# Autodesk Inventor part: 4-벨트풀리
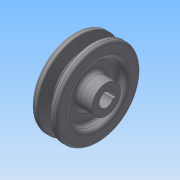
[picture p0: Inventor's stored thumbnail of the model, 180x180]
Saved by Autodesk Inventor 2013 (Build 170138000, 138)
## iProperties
Created: 2015-02
Part Number: 4-벨트풀리
Material: 일반
Document SubType Name: Modeling
Designer: Administrator
Density: 1 g/cm^3
Author: Administrator
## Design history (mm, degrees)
sketch "스케치1"
  geometry: L1 (0, 0)-(25, 0); L2 (0, 0)-(0, 11); L3 (0, 11)-(6, 11); L4 (6, 11)-(6, 21.5); L5 (6, 21.5)-(0, 21.5); L6 (0, 21.5)-(0, 32.5); L7 (0, 32.5)-(4.675, 32.5); L8 (4.675, 32.5)-(7.426, 23.5); L9 (7.426, 23.5)-(11.574, 23.5); L10 (11.574, 23.5)-(14.325, 32.5); L11 (14.325, 32.5)-(19, 32.5); L12 (19, 32.5)-(19, 21.5); L13 (19, 21.5)-(13, 21.5); L14 (13, 21.5)-(13, 11); L15 (13, 11)-(25, 11); L16 (25, 11)-(25, 0); 2 further points
  constraints: 32 end point, 6 parallel, 6 perpendicular, 5 collinear, 3 equal length, 2 point on line, 1 horizontal, 1 horizontal alignment
  dimensions: "d0" = 25 distance of L1.start L1.end; "d1" = 43 diameter of L5 L1; "d2" = 22 diameter of L3 L1; "d3" = 6 distance of L4.end L5.end; "d4" = 19 distance between parallel lines of L6 L12; "d5" = 65 diameter of L7 L1; "d6" = 8 distance of point (13.5, 29.8) point (5.5, 29.8); "d7" = 34 deg angle of L10 L8; "d8" = 2.7 distance from line of L11 point (13.5, 29.8); "d9" = 6.3 distance from line of point (13.5, 29.8) L9
revolve "회전1" sketch "스케치1" stored, may be unused: angle "d10" = 90 deg
fillet "모깎기1" dims "d11" = 3, "d12" = 2, "d13" = 1, "d14" = 0.5
sketch "스케치2"
  geometry: L1 (-2, 5.123)-(-2, 7.3); L2 (-2, 7.3)-(2, 7.3); L3 (2, 7.3)-(2, 5.123); C1 r 11 at (0, 0) reference; A1 r 5.5 centre (0, 0) between (-2, 5.123) and (2, 5.123); 1 further point
  constraints: 6 end point, 2 point on circle, 1 centre point, 1 coincident, 1 midpoint, 1 parallel, 1 perpendicular, 1 vertical, 1 vertical alignment
  dimensions: "d15" = 11 diameter of A1; "d17" = 4 distance of L1.end L2.end; "d18" = 12.8 dimension on A1 L2
extrude "돌출1" cut sketch "스케치2" stored distance "d19" = 10; taper "d20" = 0 deg
sketch "스케치3"
  geometry: 1 further point
node "솔리드1"
